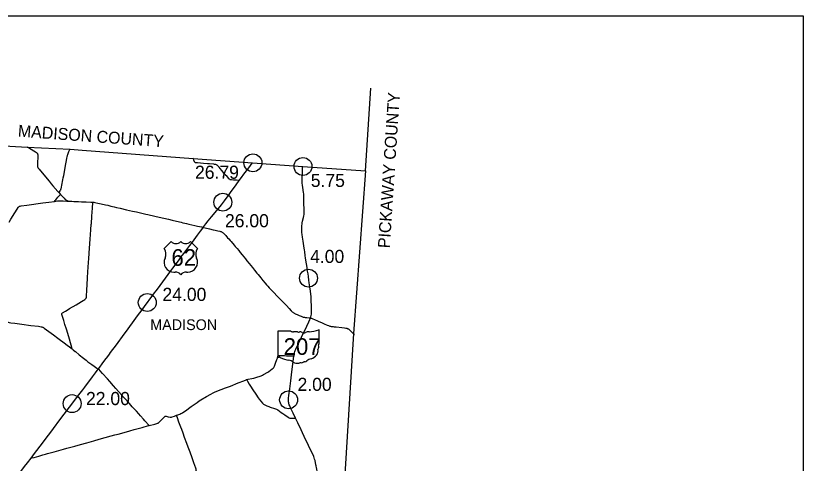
# Model space of a CAD drawing. Extents: x 1597222 to 1925846, y 496284 to 911751.
# Drawn here: x 1727439 to 1793472, y 593847 to 631367 of the extents above; entities that cross this region are included whole.
import ezdxf

# ---------------------------------------------------------------- set-up
doc = ezdxf.new("R2010")
doc.units = 0
for name, color, linetype in [('Default', 7, 'Continuous'), ('GM_X_Adjacent_County', 7, 'Continuous'), ('GM_X_Adjacent_County_Text', 7, 'Continuous'), ('GM_X_County', 7, 'Continuous'), ('GM_X_County_Road', 7, 'Continuous'), ('GM_X_State_Route', 7, 'Continuous'), ('GM_X_State_Shield', 7, 'Continuous'), ('GM_X_Township_Road', 7, 'Continuous'), ('GM_X_Township_Text', 7, 'Continuous'), ('GM_X_US_Route', 7, 'Continuous'), ('GM_X_US_Shield', 7, 'Continuous'), ('SC_Scratch1', 7, 'Continuous')]:
    doc.layers.add(name, color=color, linetype=linetype)

msp = doc.modelspace()

# ---------------------------------------------------------------- linework, layer by layer
at = {"layer": 'Default'}
for centre in [(1747325, 619038), (1747325, 619038), (1747325, 619038), (1751523, 618733), (1751523, 618733), (1751523, 618733), (1744802, 615734), (1744802, 615734), (1751988, 609367), (1751988, 609367), (1738468, 607323), (1738468, 607323), (1732165, 598849), (1732165, 598849), (1750317, 599164), (1750317, 599164)]:
    msp.add_circle(centre, 750, dxfattribs=at)
at = {"layer": 'GM_X_Adjacent_County'}
msp.add_line((1756758, 618359), (1757201, 625286), dxfattribs=at)
at = {"layer": 'GM_X_County'}
msp.add_lwpolyline([(1724957, 620538), (1728386, 620349), (1731998, 620173), (1732995, 620100), (1742304, 619412), (1747296, 619048), (1751520, 618741), (1756758, 618359), (1755763, 604727), (1755032, 592905), (1754900, 590773), (1754843, 589851), (1754339, 581698), (1753562, 571274), (1753386, 568784), (1753383, 568749), (1753220, 566444), (1752151, 553079)], dxfattribs=at)
at = {"layer": 'GM_X_County_Road'}
for points in [[(1728409, 620373), (1728512, 620310), (1728736, 620173), (1728946, 620045), (1729100, 619950), (1729167, 619903), (1729203, 619871), (1729224, 619849), (1729235, 619835), (1729252, 619807), (1729266, 619778), (1729276, 619748), (1729281, 619725), (1729284, 619700), (1729287, 619665), (1729287, 619635), (1729282, 619488), (1729267, 619078), (1729260, 618815), (1729259, 618773), (1729260, 618751), (1729262, 618735), (1729265, 618716), (1729270, 618700), (1729275, 618684), (1729283, 618665), (1729297, 618639), (1729332, 618583), (1729402, 618492), (1729644, 618202), (1730235, 617498), (1730414, 617284), (1730551, 617120), (1730954, 616644), (1731051, 616534)], [(1731051, 616534), (1731073, 616508), (1731184, 616392)], [(1731184, 616392), (1731494, 616070), (1731596, 615966), (1731648, 615924), (1731689, 615895), (1731730, 615873), (1731741, 615868)], [(1726876, 614063), (1727027, 614309), (1727364, 614853), (1727545, 615146), (1727631, 615285), (1727661, 615324), (1727680, 615344), (1727695, 615358), (1727722, 615376), (1727749, 615388), (1727769, 615396), (1727790, 615402), (1727816, 615409), (1727880, 615419), (1728367, 615486), (1729717, 615669), (1730222, 615734), (1730681, 615801)], [(1730681, 615801), (1730936, 615837), (1730980, 615842), (1731035, 615846), (1731077, 615847), (1731132, 615846), (1731426, 615836), (1731720, 615830)], [(1731720, 615830), (1731727, 615844), (1731741, 615868)], [(1731720, 615830), (1731756, 615829), (1731814, 615830), (1731824, 615831), (1731838, 615834)], [(1731741, 615868), (1731771, 615856), (1731800, 615845), (1731838, 615834)], [(1731838, 615834), (1731898, 615827), (1731994, 615820), (1732143, 615812), (1732322, 615802), (1732699, 615789), (1732962, 615779), (1733339, 615763), (1733748, 615750), (1733863, 615745), (1733909, 615742)], [(1733909, 615742), (1733929, 615740), (1733994, 615731), (1734059, 615719), (1734331, 615659), (1734603, 615598), (1734971, 615513), (1735147, 615472), (1735402, 615413), (1735690, 615347), (1735898, 615300), (1736202, 615230), (1736729, 615107), (1737240, 614989), (1737560, 614916), (1737784, 614864), (1738343, 614734), (1738501, 614698), (1739108, 614558), (1739476, 614474), (1740243, 614298), (1740547, 614228), (1741170, 614083), (1741298, 614053), (1741457, 614016), (1741470, 614013)], [(1741470, 614013), (1741617, 613979), (1741745, 613950), (1741953, 613901), (1742192, 613845), (1742448, 613786), (1742672, 613735), (1743008, 613658), (1743163, 613621)], [(1743163, 613621), (1743327, 613582), (1743695, 613498), (1743998, 613427), (1744158, 613389), (1744397, 613334), (1744541, 613301), (1744605, 613284), (1744652, 613268), (1744697, 613249), (1744741, 613226), (1744783, 613199), (1744823, 613169), (1744860, 613136), (1744907, 613090), (1744974, 613018), (1745050, 612932), (1745202, 612760), (1745299, 612649), (1745417, 612514), (1745493, 612428), (1745741, 612144), (1745848, 612019), (1745995, 611843), (1746132, 611679), (1746268, 611515), (1746433, 611311), (1746700, 610978), (1746824, 610826), (1747010, 610596), (1747145, 610431), (1747279, 610265), (1747455, 610049), (1747662, 609795), (1747766, 609668), (1747982, 609400), (1748170, 609172), (1748357, 608943), (1748472, 608804), (1748568, 608693), (1748702, 608548), (1748872, 608370), (1749098, 608133), (1749326, 607897), (1749793, 607413), (1750136, 607060), (1750376, 606813), (1750546, 606635), (1750626, 606553), (1750674, 606508), (1750711, 606476), (1750749, 606446), (1750790, 606418), (1750832, 606394), (1750876, 606374), (1751028, 606311), (1751195, 606244), (1751363, 606178), (1751485, 606130), (1751547, 606108), (1751594, 606095), (1751642, 606084), (1751706, 606073), (1751713, 606072)], [(1725853, 606038), (1726415, 605816), (1726722, 605698), (1726816, 605668), (1726896, 605650), (1727026, 605630), (1727351, 605587), (1727936, 605510), (1728701, 605408), (1729335, 605327), (1729562, 605296), (1729626, 605283), (1729673, 605269), (1729718, 605250), (1729760, 605226), (1729829, 605182), (1730604, 604603), (1730959, 604338), (1731603, 603858), (1731787, 603720), (1731905, 603631), (1732099, 603483), (1732167, 603429)], [(1751713, 606072), (1751836, 606058), (1752047, 606035), (1752110, 606028), (1752143, 606025)], [(1752143, 606025), (1752173, 606022), (1752207, 606016), (1752238, 606008), (1752285, 605992), (1752347, 605968), (1752497, 605902), (1752733, 605797)], [(1752733, 605797), (1752856, 605742), (1753066, 605649), (1753291, 605549), (1753562, 605432), (1753654, 605396), (1753715, 605374), (1753778, 605354), (1753840, 605336), (1753888, 605326), (1753936, 605317), (1753998, 605309), (1754064, 605299)], [(1754064, 605299), (1754128, 605293), (1754305, 605274), (1754794, 605219), (1755006, 605197), (1755104, 605184), (1755152, 605176), (1755200, 605165), (1755232, 605155), (1755263, 605143), (1755293, 605129), (1755336, 605105), (1755377, 605077), (1755416, 605047), (1755441, 605025), (1755487, 604978), (1755637, 604818), (1755759, 604687), (1755829, 604612)], [(1732167, 603429), (1732241, 603368)], [(1732241, 603368), (1732432, 603214)], [(1732432, 603214), (1732440, 603207), (1732756, 602951), (1733108, 602664), (1733340, 602479), (1733493, 602357), (1733641, 602245), (1733814, 602120), (1734011, 601978), (1734233, 601820), (1734326, 601755), (1734358, 601732)], [(1738615, 597012), (1738254, 597416), (1738149, 597532), (1737903, 597809), (1737754, 597978), (1737554, 598202), (1737412, 598361), (1737208, 598591), (1736981, 598848), (1736771, 599081), (1736487, 599400), (1736345, 599557), (1736063, 599874), (1735843, 600123), (1735648, 600343), (1735333, 600699), (1735126, 600933), (1734722, 601381), (1734522, 601599), (1734438, 601694), (1734401, 601731), (1734376, 601756)]]:
    msp.add_lwpolyline(points, dxfattribs=at)
at = {"layer": 'GM_X_State_Route'}
for points in [[(1752233, 606995), (1752213, 607518), (1752199, 607829), (1752184, 608025), (1752156, 608270), (1752104, 608627), (1752052, 608984), (1752018, 609211), (1751977, 609503), (1751946, 609731), (1751915, 609942), (1751913, 609953), (1751887, 610120), (1751867, 610250), (1751819, 610574), (1751748, 611044), (1751716, 611272), (1751670, 611580), (1751647, 611742), (1751626, 611888), (1751596, 612082), (1751538, 612472), (1751489, 612796), (1751457, 613023), (1751436, 613186), (1751429, 613286), (1751428, 613300), (1751428, 613447), (1751431, 613660), (1751435, 613791), (1751445, 613889), (1751464, 614002), (1751494, 614146), (1751571, 614465), (1751598, 614594), (1751611, 614691), (1751615, 614729), (1751618, 614790), (1751618, 614921), (1751611, 615282), (1751606, 615479), (1751604, 615643), (1751598, 615954), (1751592, 616249), (1751585, 616446), (1751576, 616561), (1751553, 616756), (1751518, 617000), (1751497, 617146), (1751468, 617357), (1751465, 617399), (1751462, 617455), (1751462, 617569), (1751465, 617717), (1751468, 617848), (1751474, 618094), (1751488, 618520), (1751496, 618746)], [(1751978, 595360), (1751745, 595851), (1751373, 596637), (1751082, 597243), (1750978, 597466), (1750905, 597620), (1750702, 598043), (1750491, 598488), (1750417, 598652), (1750376, 598759), (1750351, 598836), (1750332, 598916), (1750320, 598997), (1750313, 599094), (1750312, 599192), (1750314, 599237), (1750319, 599307), (1750345, 599535), (1750418, 600087), (1750504, 600771), (1750597, 601503), (1750769, 602837), (1750771, 602851), (1750791, 602983), (1750814, 603095), (1750844, 603206), (1750881, 603314), (1750918, 603405), (1751035, 603658), (1751302, 604221), (1751487, 604605), (1751669, 604991), (1752014, 605717), (1752101, 605912), (1752142, 606019), (1752143, 606025), (1752177, 606129), (1752200, 606225), (1752225, 606354), (1752239, 606468), (1752243, 606512), (1752245, 606567), (1752245, 606682), (1752236, 606928), (1752233, 606995)], [(1752572, 593893), (1752533, 594068), (1752500, 594195), (1752466, 594305), (1752425, 594412), (1752365, 594547), (1752196, 594903), (1751991, 595333), (1751978, 595360)], [(1753106, 591917), (1753037, 592014), (1752993, 592083), (1752962, 592140), (1752939, 592201), (1752922, 592264), (1752921, 592269), (1752881, 592459), (1752842, 592644), (1752803, 592829), (1752764, 593014), (1752754, 593065), (1752723, 593199), (1752696, 593319), (1752682, 593384), (1752669, 593447), (1752666, 593465), (1752629, 593636), (1752613, 593707), (1752607, 593734), (1752573, 593888), (1752572, 593893)]]:
    msp.add_lwpolyline(points, dxfattribs=at)
at = {"layer": 'GM_X_State_Shield'}
for p, q in [((1749414, 604899), (1749414, 602786)), ((1750467, 604935), (1749448, 604935)), ((1752894, 603882), (1752894, 604988)), ((1752894, 603883), (1752894, 603882))]:
    msp.add_line(p, q, dxfattribs=at)
for centre, major_axis, start_param, end_param in [((1749453, 604904), (40.3, 0), 1.712693, 3.28349), ((1750710, 605181), (391, 0), 4.042523, 4.731795), ((1750839, 603749), (1404, 0), 1.404758, 1.657858), ((1751324, 604670), (235, 0), 0.950623, 2.079405), ((1752125, 604290), (743, 0), 1.699011, 2.107814), ((1751654, 607816), (3691, 0), 4.814394, 5.042369), ((1752855, 604992), (38.7, 0), 6.141152, 7.989035), ((1751158, 604914), (113, 0), 3.836095, 5.185415), ((1751627, 605005), (282, 0), 4.081561, 5.145723), ((1753033, 603420), (262, 0), 2.387724, 3.262537), ((1752885, 603801), (60, 0), 1.883978, 3.671073), ((1752504, 603661), (360, 0), 5.934695, 6.695948), ((1752853, 603878), (41.5, 0), 5.05454, 6.418171), ((1751861, 603279), (923, 0), 5.101752, 6.440018), ((1749454, 602781), (40.7, 0), 3.00124, 4.508301), ((1749460, 602997), (310, 0), 4.665946, 4.897461), ((1749523, 602664), (112, 0), 0.519207, 1.627899), ((1750937, 604563), (2665, 0), 4.195997, 4.488961), ((1750142, 601836), (834, 0), 0.823519, 1.323587), ((1751044, 602653), (529, 0), 4.026481, 4.996735), ((1751350, 601923), (435, 0), 1.495662, 1.94098), ((1751388, 602495), (282, 0), 4.691044, 5.507374), ((1751643, 602290), (79.4, 0), 1.147584, 2.315152), ((1751610, 602581), (298, 0), 4.937069, 5.64225), ((1752250, 602192), (506, 0), 1.647645, 2.488434)]:
    msp.add_ellipse(centre, major_axis=major_axis, ratio=0.8, start_param=start_param, end_param=end_param, dxfattribs=at)
at = {"layer": 'GM_X_Township_Road'}
for points in [[(1731051, 616534), (1731069, 616558), (1731157, 616676), (1731192, 616731), (1731203, 616751), (1731210, 616766), (1731221, 616791), (1731229, 616817), (1731236, 616851), (1731264, 616985), (1731300, 617159), (1731392, 617608), (1731428, 617784), (1731465, 617977), (1731521, 618283), (1731622, 618814), (1731675, 619104), (1731729, 619394), (1731763, 619571), (1731778, 619630), (1731792, 619681), (1731814, 619744), (1731835, 619805), (1731899, 619973), (1731977, 620162)], [(1746186, 617554), (1746147, 617557), (1745938, 617574), (1745709, 617590), (1745529, 617603), (1745463, 617609), (1745447, 617612), (1745431, 617616), (1745416, 617622), (1745401, 617629), (1745387, 617638), (1745375, 617649), (1745339, 617684), (1745335, 617688), (1745158, 617880), (1745012, 618036), (1744980, 618073), (1744917, 618149), (1744722, 618391), (1744587, 618556), (1744504, 618658), (1744462, 618709), (1744419, 618758), (1744384, 618792), (1744359, 618814), (1744332, 618833), (1744304, 618850), (1744274, 618864), (1744229, 618883), (1744198, 618893), (1744166, 618901), (1744117, 618909), (1744035, 618917), (1743691, 618942), (1743528, 618954), (1743184, 618981), (1742922, 619002), (1742676, 619022), (1742578, 619030), (1742545, 619034), (1742529, 619037), (1742513, 619042), (1742498, 619048), (1742484, 619056), (1742471, 619066), (1742460, 619078), (1742450, 619091), (1742442, 619105), (1742435, 619120), (1742384, 619259), (1742340, 619383), (1742326, 619418)], [(1730681, 615801), (1730697, 615831), (1730703, 615842), (1730707, 615848), (1730711, 615852), (1730730, 615875), (1730795, 615945), (1730975, 616151), (1731028, 616212), (1731160, 616365), (1731184, 616392)], [(1732167, 603429), (1732153, 603495), (1732139, 603559), (1732088, 603749), (1732032, 603938), (1731939, 604252), (1731878, 604456), (1731686, 605083), (1731565, 605475), (1731466, 605805), (1731314, 606307), (1731307, 606339), (1731305, 606355), (1731306, 606370), (1731310, 606386), (1731316, 606402), (1731327, 606419), (1731340, 606433), (1731365, 606454), (1731604, 606598), (1731757, 606693), (1731953, 606813), (1732500, 607142), (1732726, 607276), (1732950, 607411), (1733090, 607497), (1733144, 607534), (1733243, 607590), (1733298, 607626), (1733323, 607648), (1733342, 607675), (1733356, 607704), (1733363, 607736), (1733371, 607835), (1733402, 608375), (1733428, 608817), (1733463, 609390), (1733493, 609898), (1733545, 610692), (1733570, 611017), (1733632, 611884), (1733685, 612637), (1733742, 613422), (1733776, 613903), (1733777, 613933), (1733824, 614564), (1733872, 615235), (1733907, 615710), (1733909, 615742)], [(1746789, 600858), (1746822, 600868), (1746855, 600877), (1746935, 600895), (1747242, 600945), (1747403, 600975), (1747498, 600998), (1747577, 601023), (1748023, 601187), (1748129, 601232), (1748217, 601276), (1748585, 601492), (1748668, 601545), (1748944, 601752), (1749021, 601813), (1749056, 601848), (1749086, 601888), (1749111, 601931), (1749131, 601976), (1749171, 602084), (1749225, 602239), (1749330, 602532), (1749376, 602671), (1749429, 602825), (1749437, 602841), (1749443, 602853), (1749453, 602866), (1749464, 602876), (1749477, 602885), (1749491, 602890), (1749507, 602894), (1749520, 602895), (1749538, 602895), (1749751, 602882), (1749961, 602868), (1750144, 602856), (1750299, 602852), (1750421, 602852), (1750455, 602852)], [(1750455, 602852), (1750633, 602853), (1750731, 602851), (1750771, 602851)], [(1740917, 597865), (1740945, 597875), (1741189, 597964), (1741295, 598008), (1741367, 598047), (1741437, 598091), (1741664, 598253), (1742158, 598605), (1742640, 598946), (1742829, 599076), (1742954, 599153), (1743437, 599433), (1743806, 599644), (1743992, 599747), (1744096, 599797), (1744293, 599877), (1745027, 600161), (1745441, 600319), (1746095, 600579), (1746566, 600770), (1746762, 600848), (1746789, 600858)], [(1746789, 600858), (1746804, 600832), (1746865, 600735), (1747016, 600481), (1747129, 600302), (1747328, 600003), (1747572, 599633), (1747773, 599334), (1747860, 599215), (1748131, 598887), (1748187, 598827), (1748224, 598795), (1748266, 598770), (1748489, 598666), (1748654, 598593), (1748761, 598552), (1749135, 598429), (1749306, 598371), (1749366, 598345), (1749423, 598312), (1749705, 598115), (1749839, 598021), (1750013, 597898), (1750295, 597700), (1750364, 597655), (1750408, 597634), (1750439, 597624), (1750488, 597616), (1750570, 597614), (1750604, 597614)], [(1738615, 597012), (1739105, 597135), (1739279, 597179), (1739326, 597195), (1739370, 597218), (1739411, 597246), (1739502, 597318), (1739550, 597362), (1739796, 597626), (1739932, 597768), (1739957, 597787), (1739971, 597793), (1739986, 597797), (1740002, 597800), (1740017, 597800), (1740049, 597795), (1740223, 597750), (1740382, 597712), (1740411, 597707), (1740431, 597705), (1740465, 597706), (1740498, 597711), (1740545, 597726), (1740745, 597801), (1740917, 597865)], [(1742656, 591696), (1742648, 591877), (1742638, 592138), (1742609, 592680), (1742585, 593169), (1742576, 593250), (1742568, 593295), (1742557, 593342), (1742531, 593426), (1742366, 593888), (1742220, 594309), (1742054, 594775), (1741897, 595203), (1741781, 595515), (1741603, 596005), (1741472, 596362), (1741357, 596667), (1741283, 596868), (1741127, 597297), (1740989, 597668), (1740927, 597839), (1740917, 597865)], [(1750604, 597614), (1750717, 597614), (1750815, 597616), (1750851, 597618), (1750876, 597619), (1750905, 597620)], [(1728721, 594277), (1728784, 594291), (1728800, 594295), (1728974, 594341), (1729369, 594451), (1729701, 594543), (1729922, 594604), (1730111, 594657), (1730649, 594806), (1731059, 594919), (1731438, 595027), (1731723, 595103), (1732387, 595287), (1732861, 595417), (1733398, 595568), (1733983, 595730), (1734441, 595857), (1735452, 596137), (1735737, 596216), (1736021, 596296), (1736527, 596436), (1737017, 596570), (1737364, 596667), (1738028, 596851), (1738565, 596999), (1738615, 597012)]]:
    msp.add_lwpolyline(points, dxfattribs=at)
at = {"layer": 'GM_X_US_Route'}
for points in [[(1743030, 613443), (1743163, 613621), (1743219, 613696), (1743389, 613917), (1743583, 614161), (1743862, 614505), (1744574, 615385), (1744685, 615527), (1744933, 615854), (1745244, 616276), (1745594, 616752), (1745769, 616990), (1746130, 617477), (1746186, 617554), (1746373, 617808), (1746569, 618071), (1746970, 618611), (1747271, 619016), (1747298, 619054)], [(1741081, 610826), (1741192, 610976), (1741294, 611112), (1741435, 611302), (1741633, 611564), (1741780, 611761), (1742044, 612117), (1742249, 612394), (1742534, 612775), (1742671, 612959), (1742934, 613315), (1743030, 613443)], [(1735293, 602996), (1735391, 603127), (1735879, 603786), (1736541, 604683), (1736727, 604934), (1737515, 606004), (1737740, 606307), (1737855, 606465), (1737961, 606612), (1738235, 606980), (1738937, 607930), (1739084, 608128), (1739221, 608312), (1739317, 608445), (1740448, 609975), (1740614, 610199), (1740888, 610568), (1741081, 610826)], [(1733875, 601091), (1734140, 601441), (1734278, 601624), (1734358, 601732), (1734376, 601756), (1734483, 601901), (1734688, 602178), (1734922, 602494), (1735156, 602811), (1735293, 602996)], [(1727384, 592515), (1727515, 592688), (1727591, 592795), (1727718, 592967), (1727869, 593161), (1728173, 593562), (1728421, 593879), (1728721, 594277), (1729024, 594677), (1729678, 595540), (1730065, 596050), (1730291, 596352), (1730598, 596757), (1731142, 597476), (1732319, 599033), (1732626, 599438), (1733063, 600014), (1733230, 600236), (1733873, 601087), (1733875, 601091)]]:
    msp.add_lwpolyline(points, dxfattribs=at)
at = {"layer": 'GM_X_US_Shield'}
for p, q in [((1740468, 612432), (1739888, 611852)), ((1742672, 611852), (1742092, 612432)), ((1740700, 609880), (1740816, 609880)), ((1741744, 609880), (1741860, 609880))]:
    msp.add_line(p, q, dxfattribs=at)
for centre, radius, start, end in [((1740874, 612847), 580, 225.573, 314.427), ((1741686, 612847), 580, 225.573, 314.427), ((1739222, 611387), 812, 334.54712, 35.00093), ((1743337, 611387), 812, 144.99907, 205.45288), ((1740691, 610692), 812, 154.83192, 270.63826), ((1741869, 610692), 812, 269.36174, 25.16808), ((1740816, 609300), 580, 36.8699, 90), ((1741744, 609300), 580, 90, 143.1301)]:
    msp.add_arc(centre, radius, start, end, dxfattribs=at)
at = {"layer": 'SC_Scratch1'}
msp.add_lwpolyline([(1597222, 631367), (1793472, 631367), (1793472, 496867), (1597222, 496867)], close=True, dxfattribs=at)

# ---------------------------------------------------------------- texts
at = {"layer": 'Default'}
for s, p in [('26.79', (1742470, 617697)), ('26.79', (1742470, 617697)), ('5.75', (1752178, 617011)), ('5.75', (1752178, 617011)), ('26.00', (1744982, 613633)), ('26.00', (1744982, 613633)), ('4.00', (1752121, 610639)), ('4.00', (1752121, 610639)), ('24.00', (1739741, 607455)), ('24.00', (1739741, 607455)), ('2.00', (1751067, 599914)), ('2.00', (1751067, 599914)), ('22.00', (1733329, 598724)), ('22.00', (1733329, 598724))]:
    msp.add_text(s, height=1100, dxfattribs=at).set_placement(p)
at = {"layer": 'GM_X_Adjacent_County_Text'}
for s, rotation, p in [('PICKAWAY COUNTY', 86.20343, (1758796, 611853)), ('MADISON COUNTY', 355.81897, (1727592, 621233))]:
    msp.add_text(s, height=1000, rotation=rotation, dxfattribs=at).set_placement(p)
at = {"layer": 'GM_X_State_Shield'}
msp.add_text('207', height=1392.2, dxfattribs=at).set_placement((1749899, 602935))
at = {"layer": 'GM_X_Township_Text'}
msp.add_text('MADISON', height=900, rotation=0.00001, dxfattribs=at).set_placement((1738712, 605014))
at = {"layer": 'GM_X_US_Shield'}
msp.add_text('62', height=1392.2, dxfattribs=at).set_placement((1740492, 610402))

doc.saveas('drawing.dxf')
